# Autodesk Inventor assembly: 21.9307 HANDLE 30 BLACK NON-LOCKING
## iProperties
Created: 2012-08
Part Number: 21.9307 HANDLE 30 BLACK NON-LOCKING
Document SubType Name: Assembly
Designer: Administrator
Translation Standard: STEP AP214IS
FileName: 1000-U360_ASM
PreProcessor: PRO/ENGINEER BY PARAMETRIC TECHNOLOGY CORPORATION, 2010330
PostProcessor: Build: 236a, Release: 2009 RTM - Date: Fri 02/22/2008
Sent Units: MM
Uncertainty: 0.006452648205708
Author: Administrator
